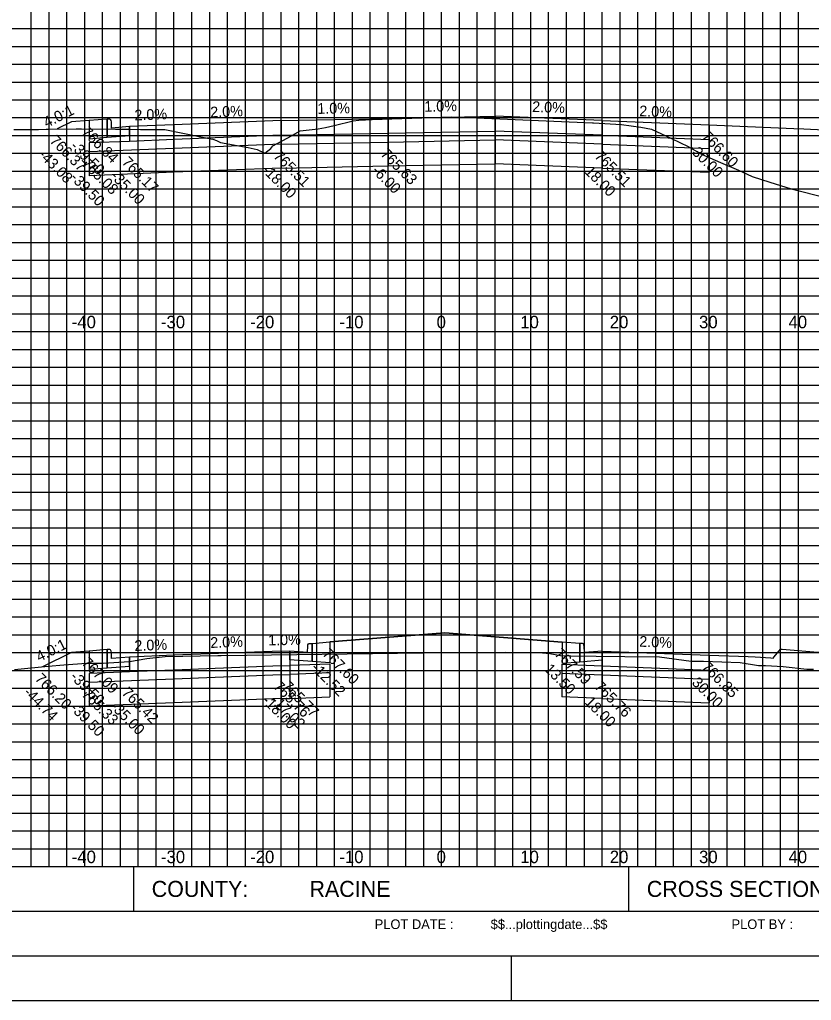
# Model space of a CAD drawing. Extents: x 578243 to 601557, y 174899 to 175559.
# Drawn here: x 601332.5 to 601421.3, y 175338.8 to 175448.8 of the extents above; entities that cross this region are included whole.
import ezdxf

# ---------------------------------------------------------------- set-up
doc = ezdxf.new("R2010")
doc.units = 0
for name, color, linetype in [('E_PROF_Grid', 7, 'Continuous'), ('E_PROF_GridMin', 7, 'Continuous'), ('P_CRDR_Label', 7, 'Continuous'), ('P_CRDR_Link', 7, 'Continuous'), ('P_E_XS_Ground', 7, 'Continuous'), ('P_SURF_Final_Top', 7, 'Continuous'), ('P_XS_Text', 7, 'Continuous'), ('PLT_Sheet_Border', 7, 'Continuous'), ('PLT_Sheet_Info', 7, 'Continuous')]:
    doc.layers.add(name, color=color, linetype=linetype)

msp = doc.modelspace()

# ---------------------------------------------------------------- linework, layer by layer
at = {"layer": 'E_PROF_Grid'}
for p, q in [((601339.84, 175353.8), (601339.84, 175548.8)), ((601349.84, 175353.8), (601349.84, 175548.8)), ((601359.84, 175353.8), (601359.84, 175548.8)), ((601369.84, 175353.8), (601369.84, 175548.8)), ((601379.84, 175353.8), (601379.84, 175548.8)), ((601389.84, 175353.8), (601389.84, 175548.8)), ((601399.84, 175353.8), (601399.84, 175548.8)), ((601409.84, 175353.8), (601409.84, 175548.8)), ((601419.84, 175353.8), (601419.84, 175548.8)), ((601229.84, 175443.8), (601544.84, 175443.8)), ((601229.84, 175433.8), (601544.84, 175433.8)), ((601229.84, 175423.8), (601544.84, 175423.8)), ((601229.84, 175413.8), (601544.84, 175413.8)), ((601229.84, 175403.8), (601544.84, 175403.8)), ((601229.84, 175393.8), (601544.84, 175393.8)), ((601229.84, 175383.8), (601544.84, 175383.8)), ((601229.84, 175373.8), (601544.84, 175373.8)), ((601229.84, 175363.8), (601544.84, 175363.8))]:
    msp.add_line(p, q, dxfattribs=at)
at = {"layer": 'E_PROF_GridMin'}
for p, q in [((601333.84, 175353.8), (601333.84, 175548.8)), ((601335.84, 175353.8), (601335.84, 175548.8)), ((601337.84, 175353.8), (601337.84, 175548.8)), ((601341.84, 175353.8), (601341.84, 175548.8)), ((601343.84, 175353.8), (601343.84, 175548.8)), ((601345.84, 175353.8), (601345.84, 175548.8)), ((601347.84, 175353.8), (601347.84, 175548.8)), ((601351.84, 175353.8), (601351.84, 175548.8)), ((601353.84, 175353.8), (601353.84, 175548.8)), ((601355.84, 175353.8), (601355.84, 175548.8)), ((601357.84, 175353.8), (601357.84, 175548.8)), ((601361.84, 175353.8), (601361.84, 175548.8)), ((601363.84, 175353.8), (601363.84, 175548.8)), ((601365.84, 175353.8), (601365.84, 175548.8)), ((601367.84, 175353.8), (601367.84, 175548.8)), ((601371.84, 175353.8), (601371.84, 175548.8)), ((601373.84, 175353.8), (601373.84, 175548.8)), ((601375.84, 175353.8), (601375.84, 175548.8)), ((601377.84, 175353.8), (601377.84, 175548.8)), ((601381.84, 175353.8), (601381.84, 175548.8)), ((601383.84, 175353.8), (601383.84, 175548.8)), ((601385.84, 175353.8), (601385.84, 175548.8)), ((601387.84, 175353.8), (601387.84, 175548.8)), ((601391.84, 175353.8), (601391.84, 175548.8)), ((601393.84, 175353.8), (601393.84, 175548.8)), ((601395.84, 175353.8), (601395.84, 175548.8)), ((601397.84, 175353.8), (601397.84, 175548.8)), ((601401.84, 175353.8), (601401.84, 175548.8)), ((601403.84, 175353.8), (601403.84, 175548.8)), ((601405.84, 175353.8), (601405.84, 175548.8)), ((601407.84, 175353.8), (601407.84, 175548.8)), ((601411.84, 175353.8), (601411.84, 175548.8)), ((601413.84, 175353.8), (601413.84, 175548.8)), ((601415.84, 175353.8), (601415.84, 175548.8)), ((601417.84, 175353.8), (601417.84, 175548.8)), ((601229.84, 175447.8), (601544.84, 175447.8)), ((601229.84, 175445.8), (601544.84, 175445.8)), ((601229.84, 175441.8), (601544.84, 175441.8)), ((601229.84, 175439.8), (601544.84, 175439.8)), ((601229.84, 175437.8), (601544.84, 175437.8)), ((601229.84, 175435.8), (601544.84, 175435.8)), ((601229.84, 175431.8), (601544.84, 175431.8)), ((601229.84, 175429.8), (601544.84, 175429.8)), ((601229.84, 175427.8), (601544.84, 175427.8)), ((601229.84, 175425.8), (601544.84, 175425.8)), ((601229.84, 175421.8), (601544.84, 175421.8)), ((601229.84, 175419.8), (601544.84, 175419.8)), ((601229.84, 175417.8), (601544.84, 175417.8)), ((601229.84, 175415.8), (601544.84, 175415.8)), ((601229.84, 175411.8), (601544.84, 175411.8)), ((601229.84, 175409.8), (601544.84, 175409.8)), ((601229.84, 175407.8), (601544.84, 175407.8)), ((601229.84, 175405.8), (601544.84, 175405.8)), ((601229.84, 175401.8), (601544.84, 175401.8)), ((601229.84, 175399.8), (601544.84, 175399.8)), ((601229.84, 175397.8), (601544.84, 175397.8)), ((601229.84, 175395.8), (601544.84, 175395.8)), ((601229.84, 175391.8), (601544.84, 175391.8)), ((601229.84, 175389.8), (601544.84, 175389.8)), ((601229.84, 175387.8), (601544.84, 175387.8)), ((601229.84, 175385.8), (601544.84, 175385.8)), ((601229.84, 175381.8), (601544.84, 175381.8)), ((601229.84, 175379.8), (601544.84, 175379.8)), ((601229.84, 175377.8), (601544.84, 175377.8)), ((601229.84, 175375.8), (601544.84, 175375.8)), ((601229.84, 175371.8), (601544.84, 175371.8)), ((601229.84, 175369.8), (601544.84, 175369.8)), ((601229.84, 175367.8), (601544.84, 175367.8)), ((601229.84, 175365.8), (601544.84, 175365.8)), ((601229.84, 175361.8), (601544.84, 175361.8)), ((601229.84, 175359.8), (601544.84, 175359.8)), ((601229.84, 175357.8), (601544.84, 175357.8)), ((601229.84, 175355.8), (601544.84, 175355.8))]:
    msp.add_line(p, q, dxfattribs=at)
at = {"layer": 'P_CRDR_Link'}
for points in [[(601373.84, 175437.72), (601385.84, 175437.96)], [(601385.84, 175437.96), (601385.84, 175436.3)], [(601397.84, 175437.48), (601385.84, 175437.96)], [(601385.84, 175437.96), (601385.84, 175436.3)], [(601338.34, 175437.32), (601336.76, 175436.53)], [(601338.34, 175437.32), (601336.76, 175436.53)], [(601340.34, 175437.48), (601338.34, 175437.32)], [(601340.34, 175437.48), (601338.34, 175437.32)], [(601342.34, 175437.64), (601340.34, 175437.48)], [(601340.34, 175437.48), (601340.34, 175435.44)], [(601340.34, 175437.48), (601340.34, 175435.44)], [(601340.34, 175437.48), (601340.34, 175435.44)], [(601342.66, 175437.64), (601342.34, 175437.64)], [(601342.66, 175437.64), (601342.34, 175437.64)], [(601342.34, 175437.64), (601342.34, 175435.6)], [(601342.34, 175435.6), (601342.34, 175437.64)], [(601342.74, 175437.6), (601342.66, 175437.64)], [(601342.74, 175437.6), (601342.66, 175437.64)], [(601342.8, 175437.48), (601342.74, 175437.6)], [(601342.8, 175437.48), (601342.74, 175437.6)], [(601342.82, 175437.32), (601342.8, 175437.48)], [(601342.82, 175437.32), (601342.8, 175437.48)], [(601342.84, 175436.64), (601342.82, 175437.32)], [(601342.84, 175436.64), (601342.82, 175437.32)], [(601344.84, 175436.8), (601342.84, 175436.64)], [(601344.84, 175436.8), (601342.84, 175436.64)], [(601349.84, 175437), (601344.84, 175436.8)], [(601344.84, 175436.8), (601344.84, 175435.14)], [(601344.84, 175435.8), (601344.84, 175436.8)], [(601361.84, 175437.48), (601349.84, 175437)], [(601349.84, 175437), (601349.84, 175435.34)], [(601349.84, 175437), (601349.84, 175435.34)], [(601361.84, 175437.48), (601373.84, 175437.72)], [(601361.84, 175437.48), (601361.84, 175435.82)], [(601361.84, 175437.48), (601361.84, 175435.82)], [(601373.84, 175437.72), (601373.84, 175436.06)], [(601373.84, 175437.72), (601373.84, 175436.06)], [(601397.84, 175437.48), (601409.84, 175437)], [(601397.84, 175437.48), (601397.84, 175435.82)], [(601397.84, 175437.48), (601397.84, 175435.82)], [(601409.84, 175437), (601409.84, 175435.34)], [(601342.34, 175435.6), (601344.84, 175435.8)], [(601342.34, 175435.6), (601344.84, 175435.8)], [(601361.84, 175435.82), (601349.84, 175435.34)], [(601361.84, 175435.82), (601373.84, 175436.06)], [(601361.84, 175435.82), (601361.84, 175434.82)], [(601361.84, 175435.82), (601361.84, 175434.82)], [(601373.84, 175436.06), (601385.84, 175436.3)], [(601373.84, 175436.06), (601373.84, 175435.06)], [(601373.84, 175436.06), (601373.84, 175435.06)], [(601385.84, 175436.3), (601385.84, 175435.3)], [(601397.84, 175435.82), (601385.84, 175436.3)], [(601385.84, 175436.3), (601385.84, 175435.3)], [(601397.84, 175435.82), (601409.84, 175435.34)], [(601397.84, 175435.82), (601397.84, 175434.82)], [(601397.84, 175435.82), (601397.84, 175434.82)], [(601340.34, 175435.44), (601342.34, 175435.6)], [(601344.84, 175435.14), (601340.34, 175434.96)], [(601340.34, 175434.96), (601340.34, 175433.96)], [(601349.84, 175435.34), (601344.84, 175435.14)], [(601349.84, 175435.34), (601349.84, 175434.34)], [(601349.84, 175435.34), (601349.84, 175434.34)], [(601361.84, 175434.82), (601349.84, 175434.34)], [(601361.84, 175434.82), (601373.84, 175435.06)], [(601361.84, 175434.82), (601361.84, 175432.15)], [(601361.84, 175434.82), (601361.84, 175432.15)], [(601373.84, 175435.06), (601385.84, 175435.3)], [(601373.84, 175435.06), (601373.84, 175432.39)], [(601373.84, 175435.06), (601373.84, 175432.39)], [(601385.84, 175435.3), (601385.84, 175432.63)], [(601397.84, 175434.82), (601385.84, 175435.3)], [(601385.84, 175435.3), (601385.84, 175432.63)], [(601397.84, 175434.82), (601409.84, 175434.34)], [(601397.84, 175434.82), (601397.84, 175432.15)], [(601397.84, 175434.82), (601397.84, 175432.15)], [(601409.84, 175435.34), (601409.84, 175434.34)], [(601349.84, 175434.34), (601340.34, 175433.96)], [(601340.34, 175433.96), (601340.34, 175431.29)], [(601349.84, 175434.34), (601349.84, 175431.67)], [(601349.84, 175434.34), (601349.84, 175431.67)], [(601409.84, 175434.34), (601409.84, 175431.67)], [(601373.84, 175432.39), (601385.84, 175432.63)], [(601397.84, 175432.15), (601385.84, 175432.63)], [(601349.84, 175431.67), (601340.34, 175431.29)], [(601361.84, 175432.15), (601349.84, 175431.67)], [(601361.84, 175432.15), (601373.84, 175432.39)], [(601397.84, 175432.15), (601409.84, 175431.67)], [(601367.32, 175379), (601380.2, 175380.03)], [(601367.32, 175379), (601380.2, 175380.03)], [(601380.2, 175380.03), (601367.32, 175379)], [(601380.2, 175380.03), (601393.34, 175378.98)], [(601380.2, 175380.03), (601393.34, 175378.98)], [(601393.34, 175378.98), (601380.2, 175380.03)], [(601364.82, 175377.84), (601364.83, 175378.52)], [(601364.82, 175377.84), (601364.83, 175378.52)], [(601364.83, 175378.52), (601364.86, 175378.68)], [(601364.83, 175378.52), (601364.86, 175378.68)], [(601364.86, 175378.68), (601364.92, 175378.8)], [(601364.86, 175378.68), (601364.92, 175378.8)], [(601364.92, 175378.8), (601365, 175378.84)], [(601364.92, 175378.8), (601365, 175378.84)], [(601365, 175378.84), (601365.32, 175378.84)], [(601365, 175378.84), (601365.32, 175378.84)], [(601365.32, 175378.84), (601367.32, 175379)], [(601365.32, 175378.84), (601365.32, 175376.8)], [(601365.32, 175376.8), (601365.32, 175378.84)], [(601367.32, 175379), (601367.32, 175376.64)], [(601367.32, 175379), (601367.32, 175376.64)], [(601367.32, 175379), (601367.32, 175376.64)], [(601367.32, 175379), (601367.32, 175379)], [(601367.32, 175379), (601367.32, 175379)], [(601367.32, 175379), (601367.32, 175379)], [(601393.34, 175378.98), (601393.33, 175378.98)], [(601393.34, 175378.98), (601393.33, 175378.98)], [(601395.34, 175378.82), (601393.34, 175378.98)], [(601393.34, 175378.98), (601393.34, 175376.62)], [(601393.34, 175378.98), (601393.34, 175376.62)], [(601393.34, 175378.98), (601393.34, 175376.62)], [(601393.34, 175378.98), (601393.34, 175378.98)], [(601395.65, 175378.82), (601395.34, 175378.82)], [(601395.65, 175378.82), (601395.34, 175378.82)], [(601395.34, 175378.82), (601395.34, 175376.78)], [(601395.34, 175376.78), (601395.34, 175378.82)], [(601395.74, 175378.78), (601395.65, 175378.82)], [(601395.74, 175378.78), (601395.65, 175378.82)], [(601395.8, 175378.66), (601395.74, 175378.78)], [(601395.8, 175378.66), (601395.74, 175378.78)], [(601395.82, 175378.5), (601395.8, 175378.66)], [(601395.82, 175378.5), (601395.8, 175378.66)], [(601395.84, 175377.82), (601395.82, 175378.5)], [(601395.84, 175377.82), (601395.82, 175378.5)], [(601338.34, 175377.82), (601335.1, 175376.2)], [(601338.34, 175377.82), (601335.1, 175376.2)], [(601340.34, 175377.98), (601338.34, 175377.82)], [(601340.34, 175377.98), (601338.34, 175377.82)], [(601342.34, 175378.14), (601340.34, 175377.98)], [(601340.34, 175377.98), (601340.34, 175375.94)], [(601340.34, 175377.98), (601340.34, 175375.94)], [(601340.34, 175377.98), (601340.34, 175375.94)], [(601342.66, 175378.14), (601342.34, 175378.14)], [(601342.66, 175378.14), (601342.34, 175378.14)], [(601342.34, 175378.14), (601342.34, 175376.1)], [(601342.34, 175376.1), (601342.34, 175378.14)], [(601342.74, 175378.1), (601342.66, 175378.14)], [(601342.74, 175378.1), (601342.66, 175378.14)], [(601342.8, 175377.98), (601342.74, 175378.1)], [(601342.8, 175377.98), (601342.74, 175378.1)], [(601342.82, 175377.82), (601342.8, 175377.98)], [(601342.82, 175377.82), (601342.8, 175377.98)], [(601342.84, 175377.14), (601342.82, 175377.82)], [(601342.84, 175377.14), (601342.82, 175377.82)], [(601349.84, 175377.5), (601344.84, 175377.3)], [(601361.84, 175377.98), (601349.84, 175377.5)], [(601349.84, 175377.5), (601349.84, 175375.84)], [(601349.84, 175377.5), (601349.84, 175375.84)], [(601361.84, 175377.98), (601362.82, 175378)], [(601361.84, 175377.98), (601361.84, 175376.32)], [(601361.84, 175377.98), (601361.84, 175376.32)], [(601362.82, 175378), (601362.82, 175376.34)], [(601362.82, 175378), (601362.82, 175376.34)], [(601362.82, 175378), (601364.82, 175377.84)], [(601362.82, 175378), (601364.82, 175377.84)], [(601362.82, 175377), (601362.82, 175378)], [(601397.84, 175377.98), (601395.84, 175377.82)], [(601397.84, 175377.98), (601395.84, 175377.82)], [(601397.84, 175377.98), (601409.84, 175377.5)], [(601397.84, 175377.98), (601397.84, 175376.32)], [(601397.84, 175377.98), (601397.84, 175376.32)], [(601397.84, 175377.98), (601397.84, 175376.32)], [(601397.84, 175376.98), (601397.84, 175377.98)], [(601409.84, 175377.5), (601409.84, 175375.84)], [(601342.34, 175376.1), (601344.84, 175376.3)], [(601342.34, 175376.1), (601344.84, 175376.3)], [(601344.84, 175377.3), (601342.84, 175377.14)], [(601344.84, 175377.3), (601342.84, 175377.14)], [(601344.84, 175377.3), (601344.84, 175375.64)], [(601344.84, 175376.3), (601344.84, 175377.3)], [(601361.84, 175376.32), (601349.84, 175375.84)], [(601361.84, 175376.32), (601362.82, 175376.34)], [(601361.84, 175376.32), (601361.84, 175375.32)], [(601361.84, 175376.32), (601361.84, 175375.32)], [(601365.32, 175376.8), (601362.82, 175377)], [(601365.32, 175376.8), (601362.82, 175377)], [(601367.32, 175376.52), (601362.82, 175376.34)], [(601362.82, 175376.34), (601362.82, 175375.34)], [(601362.82, 175376.34), (601362.82, 175375.34)], [(601367.32, 175376.64), (601365.32, 175376.8)], [(601367.32, 175376.52), (601367.32, 175375.52)], [(601393.33, 175376.5), (601397.84, 175376.32)], [(601393.33, 175376.5), (601393.33, 175375.5)], [(601393.34, 175376.62), (601395.34, 175376.78)], [(601395.34, 175376.78), (601397.84, 175376.98)], [(601395.34, 175376.78), (601397.84, 175376.98)], [(601397.84, 175376.32), (601409.84, 175375.84)], [(601397.84, 175376.32), (601397.84, 175375.32)], [(601397.84, 175376.32), (601397.84, 175375.32)], [(601397.84, 175376.32), (601397.84, 175375.32)], [(601340.34, 175375.94), (601342.34, 175376.1)], [(601344.84, 175375.64), (601340.34, 175375.46)], [(601340.34, 175375.46), (601340.34, 175374.46)], [(601349.84, 175375.84), (601344.84, 175375.64)], [(601349.84, 175375.84), (601349.84, 175374.84)], [(601349.84, 175375.84), (601349.84, 175374.84)], [(601361.84, 175375.32), (601349.84, 175374.84)], [(601361.84, 175375.32), (601362.82, 175375.34)], [(601361.84, 175375.32), (601361.84, 175372.65)], [(601361.84, 175375.32), (601361.84, 175372.65)], [(601367.32, 175375.52), (601362.82, 175375.34)], [(601362.82, 175375.34), (601362.82, 175372.67)], [(601362.82, 175375.34), (601362.82, 175372.67)], [(601367.32, 175375.52), (601367.32, 175372.85)], [(601393.33, 175375.5), (601397.84, 175375.32)], [(601393.33, 175375.5), (601393.33, 175372.83)], [(601397.84, 175375.32), (601409.84, 175374.84)], [(601397.84, 175375.32), (601397.84, 175372.65)], [(601397.84, 175375.32), (601397.84, 175372.65)], [(601397.84, 175375.32), (601397.84, 175372.65)], [(601409.84, 175375.84), (601409.84, 175374.84)], [(601349.84, 175374.84), (601340.34, 175374.46)], [(601340.34, 175374.46), (601340.34, 175371.79)], [(601349.84, 175374.84), (601349.84, 175372.17)], [(601349.84, 175374.84), (601349.84, 175372.17)], [(601409.84, 175374.84), (601409.84, 175372.17)], [(601349.84, 175372.17), (601340.34, 175371.79)], [(601361.84, 175372.65), (601349.84, 175372.17)], [(601361.84, 175372.65), (601362.82, 175372.67)], [(601362.82, 175372.67), (601367.32, 175372.85)], [(601397.84, 175372.65), (601393.33, 175372.83)], [(601397.84, 175372.65), (601409.84, 175372.17)]]:
    msp.add_lwpolyline(points, dxfattribs=at)
at = {"layer": 'P_E_XS_Ground'}
for points in [[(601331.89, 175436.47), (601334.67, 175436.49), (601335.5, 175436.52), (601335.85, 175436.52), (601338.87, 175436.56), (601339.47, 175436.53), (601343.27, 175436.52), (601344.83, 175436.5), (601346.1, 175436.49), (601348.8, 175436.48), (601353.03, 175435.6), (601353.97, 175435.44), (601354.18, 175435.38), (601354.59, 175435.24), (601355.07, 175435.03), (601358.16, 175434.46), (601359.16, 175434.22), (601360.04, 175433.82), (601360.69, 175434.35), (601360.93, 175434.63), (601361.41, 175434.92), (601362.59, 175435.55), (601363.97, 175436.31), (601365.99, 175436.56), (601366.82, 175436.7), (601367.8, 175436.91), (601369.93, 175437.43), (601370.58, 175437.52), (601372.05, 175437.58), (601379.84, 175437.85), (601380.9, 175437.89), (601382.14, 175437.85), (601383.75, 175437.78), (601396.77, 175437.22), (601396.85, 175437.22), (601400.02, 175437.02), (601402.18, 175436.72), (601403.36, 175436.52), (601405.61, 175435.48), (601407.48, 175434.58), (601408.97, 175433.71), (601411.12, 175432.77), (601413.11, 175431.9), (601414.67, 175431.21), (601416.63, 175430.56), (601419.04, 175429.82), (601423.03, 175428.79)], [(601331.98, 175375.89), (601335.74, 175376.27), (601337.51, 175376.44), (601340.05, 175376.62), (601341.91, 175376.62), (601344.87, 175376.82), (601346.78, 175377.16), (601348.86, 175377.35), (601354.75, 175377.49), (601354.95, 175377.48), (601355.12, 175377.48), (601377.75, 175377.78), (601377.75, 175377.78), (601379.84, 175377.8), (601386.95, 175377.86), (601390.75, 175377.83), (601391.96, 175377.69), (601393.15, 175377.49), (601394.34, 175377.45), (601397.18, 175377.39), (601400.38, 175377.38), (601404.27, 175377.32), (601407.82, 175376.86), (601409.21, 175376.84), (601409.21, 175376.83), (601413.29, 175376.7), (601415.37, 175376.34), (601416.15, 175376.37), (601418.12, 175376.23), (601420.8, 175375.94), (601421.53, 175375.94)]]:
    msp.add_lwpolyline(points, dxfattribs=at)
at = {"layer": 'P_SURF_Final_Top'}
for points in [[(601409.84, 175437), (601419.31, 175436.58), (601420.43, 175436.53), (601422.71, 175436.45)], [(601409.84, 175377.5), (601414.19, 175377.36), (601415, 175377.34), (601416.73, 175377.2), (601417, 175377.18), (601417.11, 175377.31), (601417.83, 175378.18), (601417.98, 175378.18), (601418, 175378.18), (601418.47, 175378.14), (601422, 175377.85), (601423.26, 175377.9), (601424.68, 175377.95), (601447.14, 175378.73), (601447.63, 175378.49), (601449.88, 175377.34)]]:
    msp.add_lwpolyline(points, dxfattribs=at)
at = {"layer": 'PLT_Sheet_Border'}
for points in [[(601217.19, 175338.8), (601557.19, 175338.8), (601557.19, 175558.8), (601217.19, 175558.8)], [(601219.59, 175343.8), (601550.59, 175343.8), (601550.59, 175553.8), (601219.59, 175553.8)]]:
    msp.add_lwpolyline(points, close=True, dxfattribs=at)
at = {"layer": 'PLT_Sheet_Info'}
for p, q in [((601229.84, 175353.8), (601544.84, 175353.8)), ((601345.34, 175348.8), (601345.34, 175353.8)), ((601400.84, 175348.8), (601400.84, 175353.8)), ((601229.84, 175348.8), (601544.84, 175348.8)), ((601387.69, 175338.8), (601387.69, 175343.8)), ((601382.69, 175338.8), (601392.69, 175338.8))]:
    msp.add_line(p, q, dxfattribs=at)

# ---------------------------------------------------------------- texts
at = {"layer": 'P_CRDR_Label'}
for s, rotation, p in [('4.0:1', 26.5651, (601335.57, 175436.65)), ('2.0%', 2.2906, (601353.93, 175437.82)), ('1.0%', 1.1458, (601365.92, 175438.22)), ('1.0%', 1.1458, (601377.91, 175438.46)), ('2.0%', 357.7094, (601389.98, 175438.45)), ('2.0%', 357.7094, (601401.98, 175437.97)), ('2.0%', 2.2906, (601345.43, 175437.48)), ('766.84', 315, (601339.41, 175436.07)), ('766.37', 315, (601335.83, 175435.12)), ('766.37', 315, (601335.83, 175435.12)), ('766.60', 315, (601408.91, 175435.59)), ('-39.50', 315, (601338.14, 175434.5)), ('-43.08', 315, (601334.55, 175433.55)), ('-43.08', 315, (601334.55, 175433.55)), ('765.17', 315, (601343.91, 175432.72)), ('765.51', 315, (601360.91, 175433.4)), ('765.51', 315, (601360.91, 175433.4)), ('765.63', 315, (601372.91, 175433.64)), ('765.51', 315, (601396.91, 175433.4)), ('765.51', 315, (601396.91, 175433.4)), ('30.00', 315, (601407.83, 175433.83)), ('765.08', 315, (601339.41, 175432.54)), ('-39.50', 315, (601338.13, 175430.98)), ('-35.00', 315, (601342.63, 175431.16)), ('-18.00', 315, (601359.62, 175431.85)), ('-18.00', 315, (601359.62, 175431.85)), ('-6.00', 315, (601371.95, 175431.76)), ('18.00', 315, (601395.79, 175431.68)), ('18.00', 315, (601395.79, 175431.68)), ('2.0%', 2.2906, (601353.93, 175378.32)), ('1.0%', 1.1458, (601360.41, 175378.61)), ('2.0%', 357.7094, (601401.98, 175378.47)), ('4.0:1', 26.5651, (601334.75, 175376.74)), ('2.0%', 2.2906, (601345.43, 175377.98)), ('767.60', 315, (601366.39, 175377.59)), ('767.59', 315, (601392.41, 175377.57)), ('767.09', 315, (601339.41, 175376.57)), ('-12.52', 315, (601365.13, 175376)), ('13.50', 315, (601391.29, 175375.85)), ('766.85', 315, (601408.91, 175376.09)), ('766.20', 315, (601334.17, 175374.79)), ('766.20', 315, (601334.17, 175374.79)), ('-39.50', 315, (601338.12, 175375.01)), ('765.76', 315, (601360.91, 175373.9)), ('765.76', 315, (601360.91, 175373.9)), ('765.77', 315, (601361.89, 175373.92)), ('765.76', 315, (601396.91, 175373.9)), ('765.76', 315, (601396.91, 175373.9)), ('765.76', 315, (601396.91, 175373.9)), ('30.00', 315, (601407.81, 175374.35)), ('-44.74', 315, (601332.9, 175373.24)), ('-44.74', 315, (601332.9, 175373.24)), ('765.33', 315, (601339.41, 175373.04)), ('765.42', 315, (601343.91, 175373.22)), ('-35.00', 315, (601342.62, 175371.67)), ('-18.00', 315, (601359.63, 175372.34)), ('-18.00', 315, (601359.63, 175372.34)), ('-17.02', 315, (601360.62, 175372.35)), ('18.00', 315, (601395.8, 175372.17)), ('18.00', 315, (601395.8, 175372.17)), ('18.00', 315, (601395.8, 175372.17)), ('-39.50', 315, (601338.11, 175371.5))]:
    msp.add_text(s, height=1.2, rotation=rotation, dxfattribs=at).set_placement(p)
at = {"layer": 'P_XS_Text'}
for s, p in [('-40', (601338.38, 175414.18)), ('-30', (601348.38, 175414.18)), ('-20', (601358.38, 175414.18)), ('-10', (601368.38, 175414.18)), ('0', (601379.28, 175414.18)), ('0', (601379.28, 175414.18)), ('10', (601388.66, 175414.18)), ('20', (601398.69, 175414.18)), ('30', (601408.7, 175414.18)), ('40', (601418.73, 175414.18)), ('-40', (601338.38, 175354.19)), ('-30', (601348.38, 175354.19)), ('-20', (601358.38, 175354.19)), ('-10', (601368.38, 175354.19)), ('0', (601379.28, 175354.19)), ('0', (601379.28, 175354.19)), ('10', (601388.66, 175354.19)), ('20', (601398.69, 175354.19)), ('30', (601408.7, 175354.19)), ('40', (601418.73, 175354.19))]:
    msp.add_text(s, height=1.4, rotation=360, dxfattribs=at).set_placement(p)
at = {"layer": 'PLT_Sheet_Info'}
for s, p in [('COUNTY:', (601347.34, 175350.4)), ('       RACINE       ', (601360.34, 175350.4)), ('CROSS SECTIONS: 58TH RD                           ', (601402.84, 175350.4))]:
    msp.add_text(s, height=1.8, dxfattribs=at).set_placement(p)
for s, p in [('PLOT DATE :', (601372.34, 175346.8)), ('$$...plottingdate...$$', (601385.34, 175346.8)), ('PLOT BY :', (601412.34, 175346.8))]:
    msp.add_text(s, height=1.08, rotation=360, dxfattribs=at).set_placement(p)

doc.saveas('drawing.dxf')
